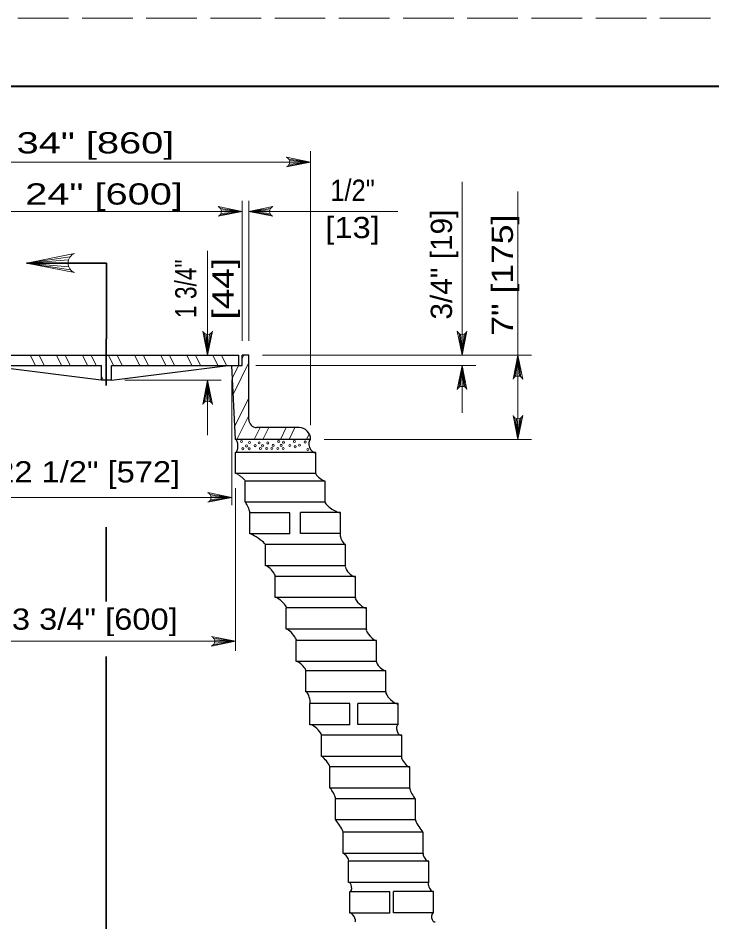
# Model space of a CAD drawing. Extents: x 1083.1 to 1117.1, y 697.4 to 741.4.
# Drawn here: x 1098.82 to 1103.92, y 734.71 to 741.35 of the extents above; entities that cross this region are included whole.
import ezdxf
from ezdxf.enums import TextEntityAlignment as Align

# ---------------------------------------------------------------- set-up
doc = ezdxf.new("R2010")
doc.units = 0
doc.header["$LTSCALE"] = 0.062
doc.linetypes.add('LONG_DASHED', pattern=[7.5, 6, -1.5])
doc.layers.add('1', color=7, linetype='Continuous', lineweight=13)

msp = doc.modelspace()

# ---------------------------------------------------------------- linework, layer by layer
at = {"layer": '1', "lineweight": 25}
for p, q in [((1085.12642, 740.85408), (1116.62642, 740.85408)), ((1098.49483, 738.87625), (1100.443, 738.87625)), ((1100.443, 738.80017), (1100.443, 738.87625)), ((1100.51608, 738.87625), (1100.46742, 738.87625)), ((1100.46742, 738.80017), (1100.46742, 738.87625)), ((1100.51608, 738.40442), (1100.51608, 738.87625)), ((1098.4705, 738.80017), (1099.43358, 738.80017)), ((1099.431, 738.692), (1098.57267, 738.80017)), ((1099.43358, 738.692), (1099.43358, 738.80017)), ((1099.5055, 738.692), (1099.5055, 738.80017)), ((1099.5055, 738.80017), (1100.46742, 738.80017)), ((1099.5055, 738.692), (1100.36383, 738.80017)), ((1099.5055, 738.692), (1099.43358, 738.692)), ((1100.88683, 738.34442), (1100.57267, 738.34442)), ((1100.41867, 738.00592), (1100.41867, 738.16192)), ((1101.00792, 738.00592), (1100.41867, 738.00592)), ((1100.48867, 737.79567), (1100.48867, 737.95158)), ((1101.07792, 737.79567), (1100.48867, 737.79567)), ((1100.81883, 737.71825), (1100.52417, 737.71825)), ((1100.52417, 737.56233), (1100.52417, 737.71825)), ((1100.81883, 737.56233), (1100.81883, 737.71825)), ((1101.18967, 737.72083), (1100.895, 737.72083)), ((1100.895, 737.56483), (1100.895, 737.72083)), ((1101.18967, 737.56483), (1101.18967, 737.72083)), ((1100.81883, 737.56233), (1100.52417, 737.56233)), ((1101.18967, 737.56492), (1100.895, 737.56492)), ((1100.63817, 737.329), (1100.63817, 737.48492)), ((1101.22742, 737.329), (1100.63817, 737.329)), ((1100.71, 737.09467), (1100.71, 737.25058)), ((1101.29925, 737.09467), (1100.71, 737.09467)), ((1100.79142, 736.86233), (1100.79142, 737.01825)), ((1101.38058, 736.86233), (1100.79142, 736.86233)), ((1100.86517, 736.62392), (1100.86517, 736.77992)), ((1101.45442, 736.62392), (1100.86517, 736.62392)), ((1100.93517, 736.40167), (1100.93517, 736.55758)), ((1101.52442, 736.40167), (1100.93517, 736.40167)), ((1101.259, 736.31575), (1100.96433, 736.31575)), ((1100.96433, 736.15975), (1100.96433, 736.31575)), ((1101.259, 736.15975), (1101.259, 736.31575)), ((1101.61342, 736.31675), (1101.31875, 736.31675)), ((1101.31875, 736.16083), (1101.31875, 736.31675)), ((1101.61342, 736.16083), (1101.61342, 736.31675)), ((1101.259, 736.15975), (1100.96433, 736.15975)), ((1101.61342, 736.16083), (1101.31875, 736.16083)), ((1101.05058, 735.92692), (1101.05058, 736.08292)), ((1101.63983, 735.92692), (1101.05058, 735.92692)), ((1101.11108, 735.69458), (1101.11108, 735.85058)), ((1101.70033, 735.69458), (1101.11108, 735.69458)), ((1101.15275, 735.46025), (1101.15275, 735.61625)), ((1101.74192, 735.46025), (1101.15275, 735.46025)), ((1101.2095, 735.21392), (1101.2095, 735.36992)), ((1101.79867, 735.21392), (1101.2095, 735.21392)), ((1101.24917, 735.00158), (1101.24917, 735.15758)), ((1101.83842, 735.00158), (1101.24917, 735.00158)), ((1101.55325, 734.93242), (1101.25858, 734.93242)), ((1101.25858, 734.77642), (1101.25858, 734.93242)), ((1101.55325, 734.77642), (1101.55325, 734.93242)), ((1101.87458, 734.93358), (1101.57992, 734.93358)), ((1101.57992, 734.77758), (1101.57992, 734.93358)), ((1101.87458, 734.77758), (1101.87458, 734.93358)), ((1101.55325, 734.77642), (1101.25858, 734.77642)), ((1101.87458, 734.77767), (1101.57992, 734.77767))]:
    msp.add_line(p, q, dxfattribs=at)
at = {"layer": '1'}
for p, q in [((1100.80983, 740.31817), (1100.97008, 740.29575)), ((1100.97008, 738.36233), (1100.97008, 740.376)), ((1097.96783, 740.29575), (1099.78475, 740.29575)), ((1099.78475, 740.29575), (1100.97008, 740.29575)), ((1100.808, 740.27092), (1100.97008, 740.29575)), ((1100.81408, 740.28133), (1100.97008, 740.29575)), ((1100.81525, 740.30708), (1100.97008, 740.29575)), ((1100.81692, 740.29575), (1100.97008, 740.29575)), ((1102.08433, 738.87625), (1102.08433, 740.14942)), ((1102.49408, 740.08008), (1102.49408, 738.25633)), ((1100.46742, 738.98225), (1100.46742, 740.01133)), ((1100.51608, 738.98225), (1100.51608, 740.01133)), ((1100.30525, 739.90792), (1100.46742, 739.93267)), ((1100.30717, 739.95508), (1100.46742, 739.93267)), ((1100.31142, 739.91825), (1100.46742, 739.93267)), ((1100.31258, 739.944), (1100.46742, 739.93267)), ((1100.31425, 739.93267), (1100.46742, 739.93267)), ((1100.67633, 739.95508), (1100.51608, 739.93267)), ((1100.67092, 739.944), (1100.51608, 739.93267)), ((1100.51608, 739.93267), (1101.61217, 739.93267)), ((1100.66925, 739.93267), (1100.51608, 739.93267)), ((1100.67208, 739.91825), (1100.51608, 739.93267)), ((1100.67817, 739.90792), (1100.51608, 739.93267)), ((1100.51608, 739.08833), (1100.51608, 739.69858)), ((1099.20208, 739.59858), (1098.88167, 739.55375)), ((1100.2135, 738.87625), (1100.2135, 739.64367)), ((1099.19125, 739.57642), (1098.88167, 739.55375)), ((1099.188, 739.55375), (1098.88167, 739.55375)), ((1099.19367, 739.52492), (1098.88167, 739.55375)), ((1099.20592, 739.50417), (1098.88167, 739.55375)), ((1100.19108, 739.0365), (1100.2135, 738.87625)), ((1100.20217, 739.03108), (1100.2135, 738.87625)), ((1100.23825, 739.03833), (1100.2135, 738.87625)), ((1100.22792, 739.03225), (1100.2135, 738.87625)), ((1100.2135, 739.02942), (1100.2135, 738.87625)), ((1102.06192, 739.0365), (1102.08433, 738.87625)), ((1102.073, 739.03108), (1102.08433, 738.87625)), ((1102.10908, 739.03833), (1102.08433, 738.87625)), ((1102.09875, 739.03225), (1102.08433, 738.87625)), ((1102.08433, 739.02942), (1102.08433, 738.87625)), ((1098.94742, 738.80017), (1098.90992, 738.87625)), ((1099.01133, 738.80017), (1098.97383, 738.87625)), ((1099.10158, 738.87625), (1099.13908, 738.80017)), ((1099.203, 738.80017), (1099.1655, 738.87625)), ((1099.33075, 738.80017), (1099.29325, 738.87625)), ((1099.39467, 738.80017), (1099.35717, 738.87625)), ((1099.52242, 738.80017), (1099.48492, 738.87625)), ((1099.58633, 738.80017), (1099.54875, 738.87625)), ((1099.71408, 738.80017), (1099.67658, 738.87625)), ((1099.77792, 738.80017), (1099.74042, 738.87625)), ((1099.90575, 738.80017), (1099.86825, 738.87625)), ((1099.96958, 738.80017), (1099.93208, 738.87625)), ((1100.09733, 738.80017), (1100.05983, 738.87625)), ((1100.34292, 738.87625), (1100.11333, 738.87625)), ((1100.16125, 738.80017), (1100.12375, 738.87625)), ((1100.289, 738.80017), (1100.2515, 738.87625)), ((1100.35292, 738.80017), (1100.31542, 738.87625)), ((1100.46742, 738.85342), (1100.47867, 738.87625)), ((1100.61625, 738.87625), (1102.59425, 738.87625)), ((1102.46933, 738.71408), (1102.49408, 738.87625)), ((1102.47975, 738.72025), (1102.49408, 738.87625)), ((1102.49408, 738.72308), (1102.49408, 738.87625)), ((1102.50542, 738.72142), (1102.49408, 738.87625)), ((1102.5165, 738.716), (1102.49408, 738.87625)), ((1100.3965, 738.70967), (1100.44108, 738.80008)), ((1100.40233, 738.59167), (1100.51608, 738.82258)), ((1100.5675, 738.80017), (1102.1845, 738.80017)), ((1102.05958, 738.638), (1102.08433, 738.80017)), ((1102.06992, 738.64417), (1102.08433, 738.80017)), ((1102.08433, 738.45367), (1102.08433, 738.80017)), ((1102.08433, 738.647), (1102.08433, 738.80017)), ((1102.09567, 738.64533), (1102.08433, 738.80017)), ((1102.10675, 738.63992), (1102.08433, 738.80017)), ((1099.44792, 738.692), (1099.43358, 738.72108)), ((1099.60558, 738.692), (1100.31367, 738.692)), ((1100.18875, 738.52983), (1100.2135, 738.692)), ((1100.19908, 738.536), (1100.2135, 738.692)), ((1100.2135, 738.692), (1100.2135, 738.28817)), ((1100.2135, 738.53883), (1100.2135, 738.692)), ((1100.22483, 738.53717), (1100.2135, 738.692)), ((1100.23592, 738.53175), (1100.2135, 738.692)), ((1100.39208, 738.69408), (1100.39208, 737.77375)), ((1100.41383, 738.35583), (1100.51608, 738.56325)), ((1100.42867, 738.25633), (1100.51608, 738.43367)), ((1102.47167, 738.41658), (1102.49408, 738.25633)), ((1102.48275, 738.41108), (1102.49408, 738.25633)), ((1102.51892, 738.41842), (1102.49408, 738.25633)), ((1102.5085, 738.41233), (1102.49408, 738.25633)), ((1102.49408, 738.4095), (1102.49408, 738.25633)), ((1100.55642, 738.25633), (1100.59983, 738.34442)), ((1100.62033, 738.25633), (1100.66375, 738.34442)), ((1100.74808, 738.25633), (1100.7915, 738.34442)), ((1100.812, 738.25633), (1100.85542, 738.34442)), ((1100.93975, 738.25633), (1100.96025, 738.29792)), ((1101.07025, 738.25633), (1102.59425, 738.25633)), ((1100.41867, 737.89992), (1100.41867, 736.70442)), ((1098.54433, 737.8305), (1100.39208, 737.8305)), ((1100.23, 737.80567), (1100.39208, 737.8305)), ((1100.23183, 737.85292), (1100.39208, 737.8305)), ((1100.23608, 737.81608), (1100.39208, 737.8305)), ((1100.23733, 737.84183), (1100.39208, 737.8305)), ((1100.23892, 737.8305), (1100.39208, 737.8305)), ((1100.25842, 736.79592), (1100.41867, 736.77342)), ((1098.51917, 736.77342), (1100.41867, 736.77342)), ((1100.25658, 736.74867), (1100.41867, 736.77342)), ((1100.26267, 736.75908), (1100.41867, 736.77342)), ((1100.26392, 736.78475), (1100.41867, 736.77342)), ((1100.2655, 736.77342), (1100.41867, 736.77342))]:
    msp.add_line(p, q, dxfattribs=at)
at = {"layer": '1', "lineweight": 35}
for p, q in [((1099.46892, 739.55375), (1098.88167, 739.55375)), ((1099.46892, 739.55375), (1099.46892, 738.99733)), ((1099.46817, 738.99733), (1099.46817, 738.65333)), ((1099.46817, 737.61217), (1099.46817, 737.06617)), ((1099.46817, 736.66258), (1099.46825, 735.21175)), ((1099.46825, 735.21175), (1099.46825, 733.86533))]:
    msp.add_line(p, q, dxfattribs=at)
at = {"layer": '1', "linetype": 'LONG_DASHED'}
msp.add_lwpolyline([(1083.12642, 719.35408), (1117.12642, 719.35408), (1117.12642, 741.35408), (1083.12642, 741.35408)], close=True, dxfattribs=at)
at = {"layer": '1', "lineweight": 40}
msp.add_lwpolyline([(1085.12642, 740.85408), (1116.62642, 740.85408), (1116.62642, 719.85408), (1085.12642, 719.85408)], close=True, dxfattribs=at)
at = {"layer": '1'}
for points in [[(1100.79308, 740.26033), (1100.97008, 740.29575), (1100.79308, 740.33117)], [(1098.46192, 739.93267), (1099.79092, 739.93267), (1100.46742, 739.93267)], [(1100.29042, 739.89725), (1100.46742, 739.93267), (1100.29042, 739.96808)], [(1100.69308, 739.89725), (1100.51608, 739.93267), (1100.69308, 739.96808)], [(1099.23567, 739.48292), (1098.88167, 739.55375), (1099.23567, 739.62458)], [(1100.24892, 739.05325), (1100.2135, 738.87625), (1100.17808, 739.05325)], [(1102.11975, 739.05325), (1102.08433, 738.87625), (1102.04892, 739.05325)], [(1102.45875, 738.69925), (1102.49408, 738.87625), (1102.5295, 738.69925)], [(1102.04892, 738.62317), (1102.08433, 738.80017), (1102.11975, 738.62317)], [(1100.17808, 738.515), (1100.2135, 738.692), (1100.24892, 738.515)], [(1102.5295, 738.43333), (1102.49408, 738.25633), (1102.45875, 738.43333)], [(1100.21508, 737.79508), (1100.39208, 737.8305), (1100.21508, 737.86592)], [(1100.24167, 736.73808), (1100.41867, 736.77342), (1100.24167, 736.80883)]]:
    msp.add_lwpolyline(points, dxfattribs=at)
at = {"layer": '1', "lineweight": 25}
for points in [[(1100.97008, 738.25633), (1100.41867, 738.25633), (1100.39208, 738.80017)], [(1101.00792, 738.00592), (1101.00792, 738.16192), (1100.41867, 738.16192)], [(1101.07792, 737.79567), (1101.07792, 737.95158), (1100.48867, 737.95158)], [(1101.22742, 737.329), (1101.22742, 737.48492), (1100.63817, 737.48492)], [(1101.29925, 737.09467), (1101.29925, 737.25058), (1100.71, 737.25058)], [(1101.38058, 736.86233), (1101.38058, 737.01825), (1100.79142, 737.01825)], [(1101.45442, 736.62392), (1101.45442, 736.77992), (1100.86517, 736.77992)], [(1101.52442, 736.40167), (1101.52442, 736.55758), (1100.93517, 736.55758)], [(1101.63983, 735.92692), (1101.63983, 736.08292), (1101.05058, 736.08292)], [(1101.70033, 735.69458), (1101.70033, 735.85058), (1101.11108, 735.85058)], [(1101.74192, 735.46025), (1101.74192, 735.61625), (1101.15275, 735.61625)], [(1101.79867, 735.21392), (1101.79867, 735.36992), (1101.2095, 735.36992)], [(1101.83842, 735.00158), (1101.83842, 735.15758), (1101.24917, 735.15758)]]:
    msp.add_lwpolyline(points, dxfattribs=at)
at = {"layer": '1'}
for centre, radius, start, end in [((1100.77881, 740.29577), 0.0382, 292.08605, 67.91218), ((1100.27608, 739.93272), 0.0382, 292.08605, 67.91218), ((1100.70736, 739.93272), 0.0382, 112.08782, 247.91395), ((1099.26422, 739.55383), 0.0764, 112.08782, 247.91395), ((1100.21347, 739.06753), 0.0382, 202.08782, 337.91395), ((1102.08429, 739.06753), 0.0382, 202.08782, 337.91395), ((1102.49416, 738.68494), 0.0382, 22.08782, 157.91395), ((1102.08437, 738.60883), 0.0382, 22.08782, 157.91395), ((1100.21354, 738.50067), 0.0382, 22.08782, 157.91395), ((1102.49408, 738.44759), 0.0382, 202.08782, 337.91395), ((1100.20082, 737.83052), 0.0382, 292.08605, 67.91218), ((1100.2274, 736.77349), 0.0382, 292.08605, 67.91218)]:
    msp.add_arc(centre, radius, start, end, dxfattribs=at)
at = {"layer": '1', "lineweight": 25}
for centre, major_axis, ratio, start_param, end_param in [((1100.5727, 738.40439), (0, 0.05997), 0.944544, 1.5707952, 3.1415937), ((1100.88686, 738.2563), (0, 0.08813), 0.944544, 4.7123842, 6.2831805), ((1100.4187, 738.2091), (0, -0.0472), 0.356664, 6.2831851, 9.4247777), ((1100.98902, 738.2091), (-0.01807, 0.04755), 0.550574, 0.0324529, 3.1740455), ((1101.04293, 737.97877), (-0.03495, 0.02724), 0.182617, 0.0102861, 3.1518788), ((1100.50645, 737.75696), (0.01773, -0.03869), 0.12471, 0.0056867, 3.1472794), ((1101.13378, 737.75823), (-0.05576, 0.03755), 0.215308, 0.0116463, 3.153239), ((1100.58118, 737.52363), (0.05694, -0.03875), 0.114762, 0.0060354, 3.1476281), ((1101.20851, 737.5249), (-0.01874, 0.04005), 0.262161, 0.0128537, 3.1544464), ((1100.67409, 737.28978), (0.03583, -0.0393), 0.2262, 0.0136046, 3.1551973), ((1101.26333, 737.28977), (-0.03567, 0.03945), 0.332158, 0.0213096, 3.1629023), ((1100.75071, 737.05644), (0.04056, -0.03832), 0.228756, 0.0136823, 3.155275), ((1101.33994, 737.05644), (-0.04055, 0.03833), 0.239953, 0.0144322, 3.1560248), ((1100.82827, 736.8211), (0.03679, -0.04129), 0.204334, 0.0121564, 3.1537491), ((1101.41751, 736.8211), (-0.03675, 0.04132), 0.238818, 0.0144388, 3.1560314), ((1100.90016, 736.59077), (0.0349, -0.03329), 0.223095, 0.0133225, 3.1549152), ((1101.4894, 736.59077), (-0.03485, 0.03334), 0.271388, 0.0166254, 3.158218), ((1100.94977, 736.35868), (0.0145, -0.04299), 0.258559, 0.0100835, 3.1516762), ((1101.56889, 736.35921), (-0.0443, 0.04264), 0.279847, 0.0172411, 3.1588337), ((1101.00747, 736.12134), (0.04296, -0.03859), 0.241358, 0.0144197, 3.1560124), ((1101.62659, 736.12187), (-0.01262, 0.03917), 0.542882, 0.0279504, 3.169543), ((1101.08083, 735.88876), (0.03022, -0.03823), 0.155778, 0.0089758, 3.1505685), ((1101.67006, 735.88876), (-0.03009, 0.03834), 0.282428, 0.0172571, 3.1588498), ((1101.13191, 735.65543), (0.02077, -0.03921), 0.149207, 0.0074425, 3.1490352), ((1101.72114, 735.65543), (-0.02076, 0.03922), 0.156228, 0.00781, 3.1494027), ((1101.18109, 735.41508), (0.02835, -0.04521), 0.098077, 0.0052123, 3.146805), ((1101.77033, 735.41508), (-0.02835, 0.04522), 0.114707, 0.006118, 3.1477107), ((1101.22934, 735.18575), (0.01976, -0.02825), 0.258713, 0.0151769, 3.1567696), ((1101.81857, 735.18575), (-0.01967, 0.02832), 0.336532, 0.020776, 3.1623686), ((1101.25391, 734.967), (0.0045, -0.03465), 0.523289, 0.0116007, 3.1531933), ((1101.8565, 734.9676), (-0.01779, 0.03418), 0.380519, 0.0217078, 3.1633005), ((1101.27755, 734.74368), (0.01867, -0.03291), 0.376867, 0.022341, 3.1639336), ((1101.88015, 734.74428), (-0.00516, 0.03342), 0.625583, 0.0201562, 3.1617488)]:
    msp.add_ellipse(centre, major_axis=major_axis, ratio=ratio, start_param=start_param, end_param=end_param, dxfattribs=at)
at = {"layer": '1'}
for centre in [(1100.46144, 738.24136), (1100.47209, 738.18904), (1100.49963, 738.20917), (1100.5187, 738.18873), (1100.52172, 738.23515), (1100.5627, 738.21165), (1100.59298, 738.23176), (1100.60096, 738.19107), (1100.61753, 738.21128), (1100.64756, 738.19076), (1100.65603, 738.23134), (1100.68594, 738.1905), (1100.69431, 738.21367), (1100.72981, 738.19021), (1100.73561, 738.24241), (1100.75462, 738.21326), (1100.76819, 738.18995), (1100.77121, 738.23637), (1100.81767, 738.21283), (1100.85075, 738.24164), (1100.856, 738.20387), (1100.88897, 738.21526), (1100.93023, 738.2382), (1100.94909, 738.18292)]:
    msp.add_ellipse(centre, major_axis=(0, 0.00779), ratio=0.944544, dxfattribs=at)
msp.add_ellipse((1100.4537, 737.97877), major_axis=(0.03496, -0.02722), ratio=0.153945, start_param=0.0085851, end_param=3.1501778, dxfattribs=at)

# ---------------------------------------------------------------- texts
for s, width, p in [('34" [860]', 1.4, (1098.80908, 740.35925)), ('24" [600]', 1.4, (1098.87233, 739.98325)), ('22 1/2" [572]', 1.15, (1098.659, 737.94108)), ('23 3/4" [600]', 1.15, (1098.64092, 736.85858))]:
    msp.add_text(s, height=0.156, dxfattribs=dict(at, width=width)).set_placement(p)
for s, width, p in [('1/2"', 0.9, (1101.2785, 740.01075)), ('[13]', 1.15, (1101.2785, 739.73675))]:
    msp.add_text(s, height=0.156, dxfattribs=dict(at, width=width)).set_placement(p, align=Align.CENTER)
for s, width, p in [('3/4" [19]', 1.05, (1102.00958, 739.13825)), ('7" [175]', 1.25, (1102.45775, 739.01967))]:
    msp.add_text(s, height=0.156, rotation=90, dxfattribs=dict(at, width=width)).set_placement(p)
for s, width, p in [('1 3/4"', 0.8, (1100.13067, 739.36471)), ('[44]', 1.3, (1100.40467, 739.36467))]:
    msp.add_text(s, height=0.156, rotation=90, dxfattribs=dict(at, width=width)).set_placement(p, align=Align.CENTER)

doc.saveas('drawing.dxf')
